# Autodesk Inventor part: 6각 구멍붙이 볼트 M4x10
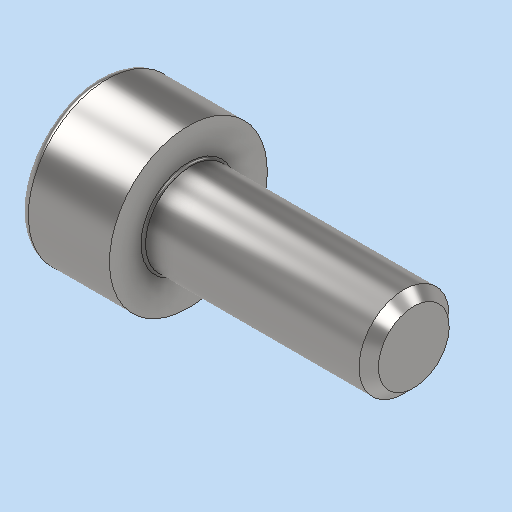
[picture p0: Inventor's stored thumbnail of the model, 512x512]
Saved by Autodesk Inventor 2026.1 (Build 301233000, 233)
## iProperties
Created: 2026-01
Part Number: 6각 구멍붙이 볼트 M4x10
Material: 강철, 연강
Description: 6각머리 태핑 나사
Document SubType Name: Modeling
Designer: PC-30
Density: 7.85 g/cm^3
Appearance: 기본값
Author: jhkim
Sending System: Autodesk Inventor 2026
Preprocessor: ST-DEVELOPER v20.1
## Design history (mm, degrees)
feature "Solid1"
node "솔리드1"
